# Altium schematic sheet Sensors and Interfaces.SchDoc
size A3; CompanyName: Icoteq Ltd; Address1: Cambridge House; Address2: 1 Henry Street; Address3: Bath; Address4: BA1 1BT; DocumentNumber: Sensors and Interfaces; SheetNumber: 4
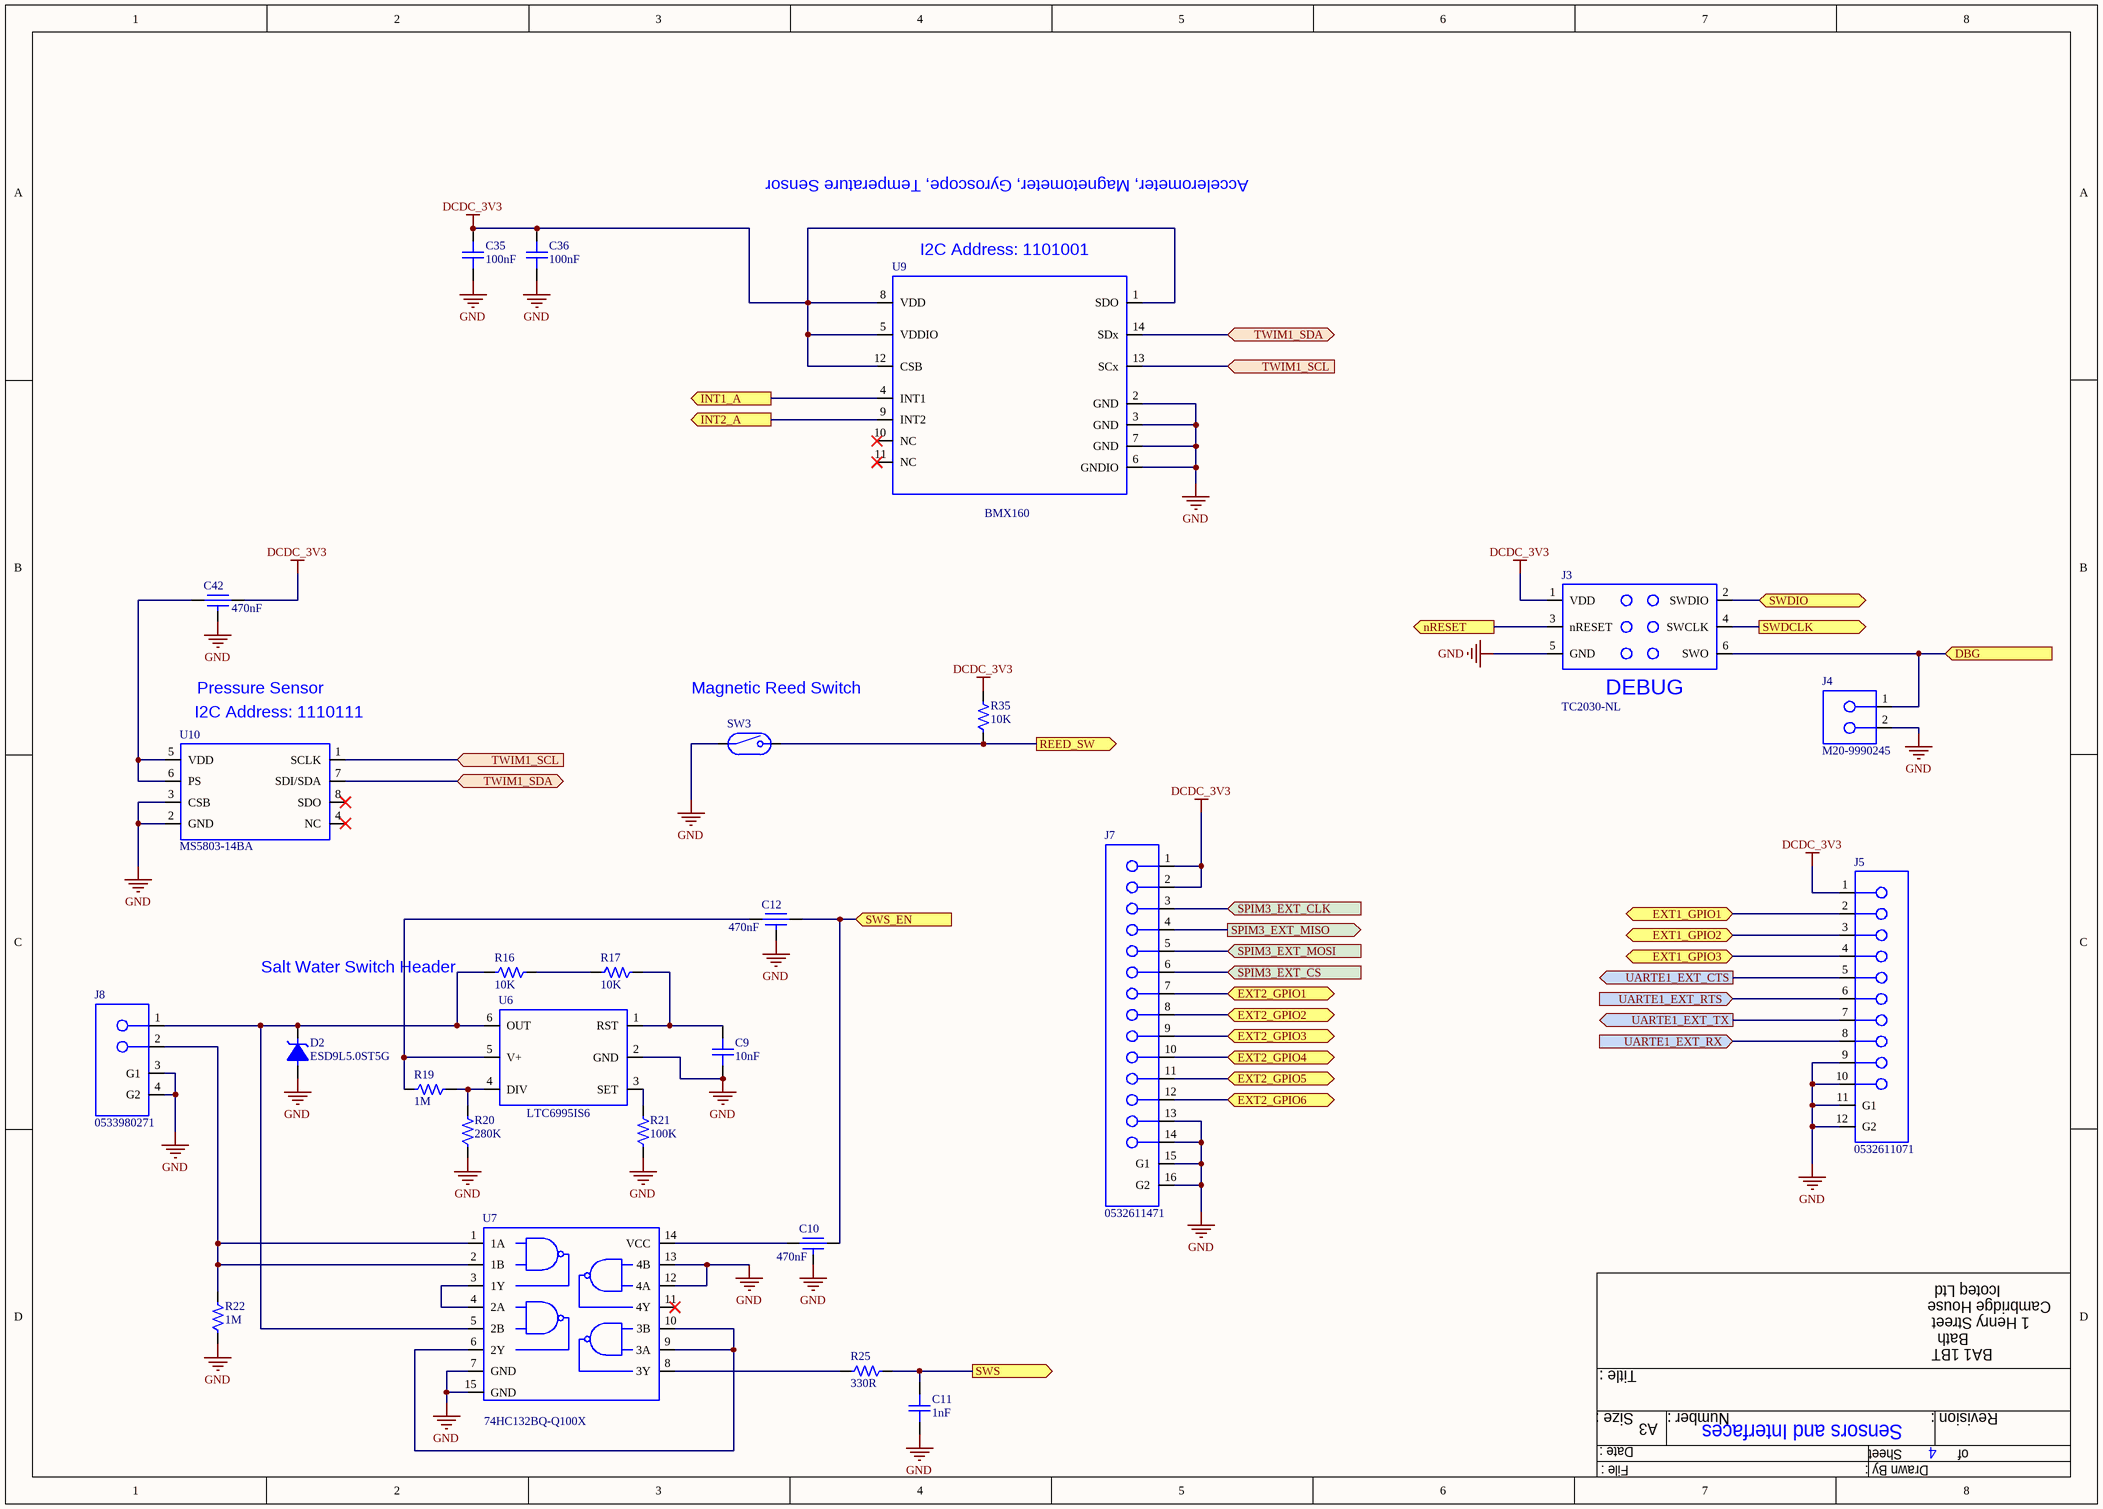
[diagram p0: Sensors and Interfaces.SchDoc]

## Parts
C9  value 10nF  [CAP0402N]  (hidden comment: 10NF 0402 16V 20% X7R)
C10  value 470nF  [YFF15PC]  (hidden comment: 470NF 0402 6.3V +50%/-20%)
C11  value 1nF  [CAP0402N]  (hidden comment: 1NF 0402 50V 5%)
C12  value 470nF  [YFF15PC]  (hidden comment: 470NF 0402 6.3V +50%/-20%)
C35  value 100nF  [CAP0201L]  (hidden comment: 100NF 0201 35V 10% X5R)
C36  value 100nF  [CAP0201L]  (hidden comment: 100NF 0201 35V 10% X5R)
C42  value 470nF  [YFF15PC]  (hidden comment: 470NF 0402 6.3V +50%/-20%)
D2  ESD9L5.0ST5G  [SOD-923]
J3  TC2030-NL  [TC2030NL]
J4  M20-9990245  [HDR 2POS 2.54MM THRU HOLE]
J5  0532611071  [0532611071]
J7  0532611471  [0532611471]
J8  0533980271  [0533980271]
R16  value 10K  [RES0402N]  (hidden comment: 10K 0402 1%)
R17  value 10K  [RES0402N]  (hidden comment: 10K 0402 1%)
R19  value 1M  [RES0402N]  (hidden comment: 1M 0402 1%)
R20  value 280K  [RES0402N]  (hidden comment: 280K 0402 1% 100PPM)
R21  value 100K  [RES0402N]  (hidden comment: 100K 0402 1%)
R22  value 1M  [RES0402N]  (hidden comment: 1M 0402 1%)
R25  value 330R  [RES0201N]  (hidden comment: 330R 0201 1% 100PPM)
R35  value 10K  [RES0201L]  (hidden comment: 10K 0201 1% 100PPM)
SW3  SW REED SPST  [CT05]  (value not drawn)
U6  LTC6995IS6  [SOT-23_DBV]
U7  74HC132BQ-Q100X  [DHVQFN14]
U9  BMX160  [LGA14]
U10  MS5803-14BA  [MS5803]

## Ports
DBG (in), EXT1_GPIO1 (bidir), EXT1_GPIO2 (bidir), EXT1_GPIO3 (bidir), EXT2_GPIO1 (bidir), EXT2_GPIO2 (bidir), EXT2_GPIO3 (bidir), EXT2_GPIO4 (bidir), EXT2_GPIO5 (bidir), EXT2_GPIO6 (bidir), INT1_A (out), INT2_A (out), nRESET (out), REED_SW (out), SPIM3_EXT_CLK (in), SPIM3_EXT_CS (in), SPIM3_EXT_MISO (out), SPIM3_EXT_MOSI (in), SWDCLK (out), SWDIO (bidir), SWS (out), SWS_EN (in), TWIM1_SCL (in), TWIM1_SDA (bidir), UARTE1_EXT_CTS (out), UARTE1_EXT_RTS (in), UARTE1_EXT_RX (in), UARTE1_EXT_TX (out)

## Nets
DCDC_3V3: C35.2 C36.2 C42.2 J3.1(VDD) J5.1 J7.1 J7.2 R35.2 U9.1(SDO) U9.5(VDDIO) U9.8(VDD) U9.12(CSB)
GND: C9.1 C10.3 C11.1 C12.3 C35.1 C36.1 C42.3 D2.1 J3.5(GND) J4.2 J5.9 J5.10 J5.11(G1) J5.12(G2) J7.13 J7.14 J7.15(G1) J7.16(G2) J8.3(G1) J8.4(G2) R20.1 R21.1 R22.1 SW3.1 U6.2(GND) U7.7(GND) U7.12(4A) U7.13(4B) U7.15(GND) U9.2(GND) U9.3(GND) U9.6(GNDIO) U9.7(GND) U10.2(GND) U10.3(CSB)
DBG: J3.6(SWO) J4.1 ; port DBG
EXT1_GPIO1: J5.2 ; port EXT1_GPIO1
EXT1_GPIO2: J5.3 ; port EXT1_GPIO2
EXT1_GPIO3: J5.4 ; port EXT1_GPIO3
EXT2_GPIO1: J7.7 ; port EXT2_GPIO1
EXT2_GPIO2: J7.8 ; port EXT2_GPIO2
EXT2_GPIO3: J7.9 ; port EXT2_GPIO3
EXT2_GPIO4: J7.10 ; port EXT2_GPIO4
EXT2_GPIO5: J7.11 ; port EXT2_GPIO5
EXT2_GPIO6: J7.12 ; port EXT2_GPIO6
INT1_A: U9.4(INT1) ; port INT1_A
INT2_A: U9.9(INT2) ; port INT2_A
nRESET: J3.3(nRESET) ; port nRESET
REED_SW: R35.1 SW3.2 ; port REED_SW
SPIM3_EXT_CLK: J7.3 ; port SPIM3_EXT_CLK
SPIM3_EXT_CS: J7.6 ; port SPIM3_EXT_CS
SPIM3_EXT_MISO: J7.4 ; port SPIM3_EXT_MISO
SPIM3_EXT_MOSI: J7.5 ; port SPIM3_EXT_MOSI
SWDCLK: J3.4(SWCLK) ; port SWDCLK
SWDIO: J3.2(SWDIO) ; port SWDIO
SWS: C11.2 R25.2 ; port SWS
SWS_EN: C10.2 C12.1 ; port SWS_EN
TWIM1_SCL: U9.13(SCx) U10.1(SCLK) ; port TWIM1_SCL
TWIM1_SDA: U9.14(SDx) U10.7(SDI/SDA) ; port TWIM1_SDA
UARTE1_EXT_CTS: J5.5 ; port UARTE1_EXT_CTS
UARTE1_EXT_RTS: J5.6 ; port UARTE1_EXT_RTS
UARTE1_EXT_RX: J5.8 ; port UARTE1_EXT_RX
UARTE1_EXT_TX: J5.7 ; port UARTE1_EXT_TX
NetC9_2: C9.2 R17.2 U6.1(RST)
NetC10_1: C10.1 U7.14(VCC)
NetC12_2: C12.2 R19.2 U6.5(V+)
NetC42_1: C42.1 U10.5(VDD) U10.6(PS)
NetD2_2: D2.2 J8.1 R16.1 U6.6(OUT) U7.5(2B)
NetJ8_2: J8.2 R22.2 U7.1(1A) U7.2(1B)
NetR16_2: R16.2 R17.1
NetR19_1: R19.1 R20.2 U6.4(DIV)
NetR21_2: R21.2 U6.3(SET)
NetR25_1: R25.1 U7.8(3Y)
NetU7_3: U7.3(1Y) U7.4(2A)
NetU7_6: U7.6(2Y) U7.9(3A) U7.10(3B)

Not connected (* = marked no-connect by the designer): U7 11(4Y)*; U9 10(NC)* 11(NC)*; U10 4(NC)* 8(SDO)*

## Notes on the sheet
- Accelerometer, Magnetometer, Gyroscope, Temperature Sensor
- (near U9) I2C Address: 1101001
- (near U10) I2C Address: 1110111
- Pressure Sensor
- (near SW3) Magnetic Reed Switch
- Salt Water Switch Header

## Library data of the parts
C9 = CAP CER 10NF 0402 16V 20% X7R: Manufacturer: AVX; Manufacturers Part Number: 0402YC103MAT2A
C10 C12 C42 = CAP FEEDTHRU 470NF 0402 6.3V +50%/-20%: Manufacturer: TDK; Manufacturers Part Number: YFF15PC0J474M
C11 = CAP CER 1NF 0402 50V 5% C0G: Manufacturer: Murata; Manufacturers Part Number: GRM1555C1H102JA01D
C35 C36 = CAP CER 100NF 0201 35V 10% X5R: Manufacturer: Murata; Manufacturers Part Number: GRM033R6YA104KE14D
D2 = ESD9L5.0ST5G: DIO TVS 5.4V 1A SOD-923; Manufacturer: ON Semiconductor
J3 = TC2030-NL: CON PLUG OF NAILS 6 PIN FOOTPRINT NO LEGS; Manufacturer: Tag-Connect; Manufacturers Part Number: NOT FITTED PART
J4 = M20-9990245: CON HDR 2POS HEADER 2.54MM VERT THRU HOLE; Manufacturer: Harwin
J5 = 0532611071: CON PICOBLADE 10POS HEADER 1.25MM HORIZ SMD; Manufacturer: Molex; ALT Manufacturer: Taicom; ALT Manufacturers Part Number: TKH10MRLSM
J7 = 0532611471: CON PICOBLADE 14POS HEADER 1.25MM HORIZ SMD; Manufacturer: Molex; ALT Manufacturer: Taicom; ALT Manufacturers Part Number: TKH14MRLSM
J8 = 0533980271: CON PICOBLADE 2POS HEADER 1.25MM VERT SMD; Manufacturer: Molex; ALT Manufacturer: Taicom; ALT Manufacturers Part Number: TKH02MSLSM
R16 R17 = RES 10K 0402 1% 100PPM: PPM: 100
R19 R22 = RES 1M 0402 1% 100PPM: PPM: 100
R20 = RES 280K 0402 1% 100PPM: PPM: 100
R21 = RES 100K 0402 1% 100PPM: PPM: 100
R25 = RES 330R 0201 1% 100PPM: PPM: 100
R35 = RES 10K 0201 1% 100PPM: PPM: 100
SW3 = SW REED SPST: SW REED SPST SMD; Manufacturer: Coto Technology; Manufacturers Part Number: CT05-1535-J1
U6 = LTC6995IS6: IC PULSE GENERATOR SOT23-6; Manufacturer: Analog Devices; Manufacturers Part Number: LTC6995IS6-1
U7 = 74HC132BQ-Q100X: IC LOGIC NAND 2-INPUT QUAD 14-DHVQFN; Manufacturer: Nexperia
U9 = BMX160: IC IMU Accel/Gyro/magnet/temp SPI/I2C 12LGA; Manufacturer: Bosch Sensortec
U10 = MS5803-14BA: IC SENSOR PRESSURE 0-14BAR SO8; Manufacturer: TE Connectivity; Manufacturers Part Number: MS580314BA01-00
